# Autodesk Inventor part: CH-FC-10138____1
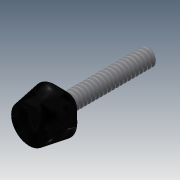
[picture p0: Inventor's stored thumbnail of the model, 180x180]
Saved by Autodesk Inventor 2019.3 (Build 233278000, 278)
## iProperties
Created: 2012-09
Part Number: CH-FC-10138____1
Material: Ogólny
Document SubType Name: Modeling
Designer: CADENGINEERING4
Density: 1 g/cm^3
Appearance: Domyślna
Author: CADENGINEERING4
Revision Number: ÈÎºÎ
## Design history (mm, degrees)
feature "NONE"
node "Bryła1"
